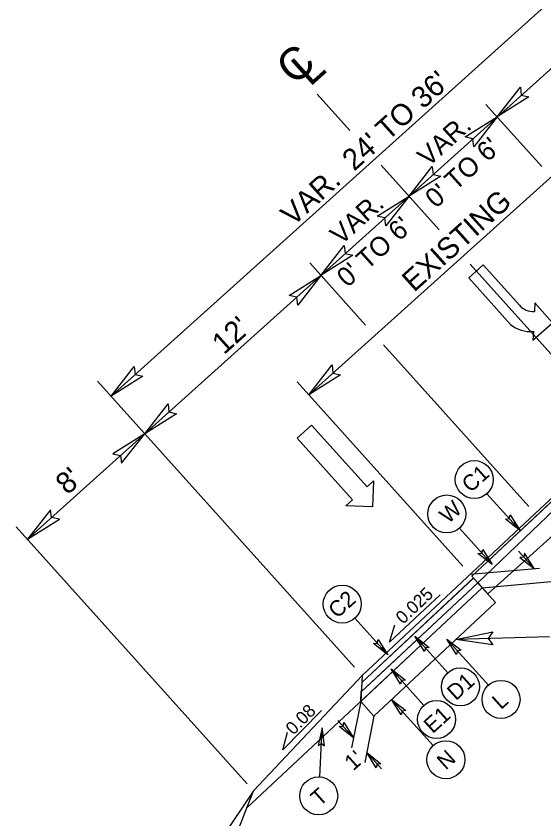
# Model space of a CAD drawing. Extents: x 2488411 to 2488707, y 383669 to 383962.
# Drawn here: x 2488590.73 to 2488617.46, y 383804.17 to 383844.82 of the extents above; entities that cross this region are included whole.
import ezdxf

# ---------------------------------------------------------------- set-up
doc = ezdxf.new("R2010")
doc.units = 0
for name, color, linetype in [('Old_Level_44', 7, 'Continuous'), ('Prop Dimension', 7, 'Continuous'), ('Prop DSN Text', 7, 'Continuous'), ('Prop Paint Stripe', 7, 'Continuous'), ('Prop Rip Rap Related Quantities Text', 7, 'Continuous'), ('Prop Roadway Profile Bench Mark Info Text', 7, 'Continuous'), ('Prop ROW RW Lines', 7, 'Continuous'), ('Sheet Data Field CELL', 7, 'Continuous'), ('Sheet Plan CELL', 7, 'Continuous'), ('Sheet Sticker Incomplete CELL', 7, 'Continuous'), ('Sheet Sticker Preliminary CELL', 7, 'Continuous'), ('Sheet Symbology CELL', 7, 'Continuous'), ('Sheet Title CELL', 7, 'Continuous'), ('Typical Hinge Slope Arterial CELL', 7, 'Continuous'), ('Typical Terminator CELL', 7, 'Continuous'), ('Typical Text ID Circle CELL', 7, 'Continuous')]:
    doc.layers.add(name, color=color, linetype=linetype)

msp = doc.modelspace()

# ---------------------------------------------------------------- linework, layer by layer
at = {"layer": 'Prop Dimension'}
msp.add_line((2488617.748, 383813.385), (2488612.992, 383813.253), dxfattribs=at)
at = {"layer": 'Prop DSN Text'}
for p, q in [((2488614.573, 383820.637), (2488616.234, 383818.788)), ((2488613.183, 383818.893), (2488614.844, 383817.045)), ((2488607.885, 383814.329), (2488609.547, 383812.481)), ((2488612.591, 383811.571), (2488610.929, 383813.42)), ((2488614.645, 383810.934), (2488612.544, 383813.271)), ((2488611.379, 383809.917), (2488609.717, 383811.766)), ((2488611.849, 383807.88), (2488609.748, 383810.218)), ((2488606.103, 383806.294), (2488606.235, 383808.777))]:
    msp.add_line(p, q, dxfattribs=at)
for centre in [(2488613.93, 383821.352), (2488612.54, 383819.608), (2488607.242, 383815.044), (2488613.234, 383810.856), (2488615.288, 383810.219), (2488612.022, 383809.202), (2488612.492, 383807.165), (2488606.052, 383805.334)]:
    msp.add_circle(centre, 0.962, dxfattribs=at)
at = {"layer": 'Prop Paint Stripe'}
for points in [[(2488615.748, 383819.561), (2488616.234, 383818.788), (2488615.51, 383819.354), (2488615.706, 383819.376)], [(2488614.358, 383817.818), (2488614.844, 383817.045), (2488614.12, 383817.611), (2488614.316, 383817.632)], [(2488616.247, 383817.408), (2488616.964, 383816.843), (2488616.478, 383817.623), (2488616.436, 383817.43)], [(2488609.06, 383813.254), (2488609.547, 383812.481), (2488608.823, 383813.047), (2488609.018, 383813.068)], [(2488611.416, 383812.647), (2488610.929, 383813.42), (2488611.653, 383812.854), (2488611.458, 383812.832)], [(2488613.031, 383812.498), (2488612.544, 383813.271), (2488613.268, 383812.705), (2488613.072, 383812.684)], [(2488610.204, 383810.993), (2488609.717, 383811.766), (2488610.441, 383811.2), (2488610.246, 383811.178)], [(2488610.235, 383809.445), (2488609.748, 383810.218), (2488610.472, 383809.651), (2488610.277, 383809.63)], [(2488606.342, 383807.87), (2488606.235, 383808.777), (2488606.027, 383807.881), (2488606.193, 383807.988)], [(2488607.329, 383809.046), (2488607.816, 383808.273), (2488607.092, 383808.839), (2488607.287, 383808.86)], [(2488608.971, 383806.756), (2488608.484, 383807.529), (2488609.208, 383806.963), (2488609.012, 383806.942)]]:
    msp.add_lwpolyline(points, close=True, dxfattribs=at)
at = {"layer": 'Prop Rip Rap Related Quantities Text'}
for p, q in [((2488613.805, 383816.458), (2488621.477, 383823.637)), ((2488617.012, 383819.63), (2488621.392, 383823.728)), ((2488608.251, 383811.432), (2488617.012, 383819.63)), ((2488608.207, 383810.596), (2488614.111, 383816.121)), ((2488608.232, 383811.072), (2488613.891, 383816.367)), ((2488614.332, 383815.876), (2488613.807, 383816.46)), ((2488602.404, 383804.714), (2488614.332, 383815.876)), ((2488608.86, 383810.755), (2488614.332, 383815.876)), ((2488614.332, 383815.876), (2488615, 383815.132)), ((2488615, 383815.132), (2488608.85, 383809.377)), ((2488608.251, 383811.432), (2488608.182, 383810.121)), ((2488608.182, 383810.121), (2488608.85, 383809.377))]:
    msp.add_line(p, q, dxfattribs=at)
at = {"layer": 'Prop Roadway Profile Bench Mark Info Text'}
for p, q in [((2488609.641, 383813.125), (2488612.2, 383815.52)), ((2488609.641, 383813.125), (2488609.907, 383814.001)), ((2488604.239, 383807.667), (2488606.191, 383809.653)), ((2488604.239, 383807.667), (2488604.468, 383808.553))]:
    msp.add_line(p, q, dxfattribs=at)
at = {"layer": 'Prop ROW RW Lines'}
for p, q in [((2488614.387, 383832.225), (2488613.651, 383831.564)), ((2488616.222, 383830.184), (2488614.387, 383832.225)), ((2488613.651, 383831.564), (2488615.767, 383829.21)), ((2488617.004, 383830.302), (2488616.98, 383829.857)), ((2488617.895, 383829.288), (2488617.004, 383830.302)), ((2488616.904, 383828.416), (2488617.895, 383829.288)), ((2488616.927, 383828.861), (2488616.904, 383828.416)), ((2488604.956, 383823.45), (2488605.692, 383824.112)), ((2488605.692, 383824.112), (2488608.5, 383820.989)), ((2488607.763, 383820.327), (2488604.956, 383823.45)), ((2488608.5, 383820.989), (2488608.834, 383821.29)), ((2488608.834, 383821.29), (2488608.774, 383819.965)), ((2488607.429, 383820.026), (2488607.763, 383820.327)), ((2488608.774, 383819.965), (2488607.429, 383820.026))]:
    msp.add_line(p, q, dxfattribs=at)
for centre, radius, start, end in [((2488616.951, 383830.835), 0.982, 221.9538, 271.612), ((2488616.763, 383830.424), 1.576, 230.6299, 275.9416)]:
    msp.add_arc(centre, radius, start, end, dxfattribs=at)
at = {"layer": 'Sheet Data Field CELL'}
for p, q in [((2488613.889, 383816.366), (2488608.232, 383811.072)), ((2488614.111, 383816.121), (2488613.889, 383816.366)), ((2488608.232, 383811.072), (2488608.207, 383810.596))]:
    msp.add_line(p, q, dxfattribs=at)
msp.add_lwpolyline([(2488608.207, 383810.596), (2488608.639, 383811.001), (2488614.111, 383816.121)], dxfattribs=at)
at = {"layer": 'Sheet Plan CELL'}
for p, q in [((2488598.022, 383793.579), (2488602.748, 383805.589)), ((2488602.748, 383805.589), (2488598.137, 383798.755))]:
    msp.add_line(p, q, dxfattribs=at)
at = {"layer": 'Sheet Sticker Incomplete CELL'}
msp.add_line((2488602.748, 383805.589), (2488608.251, 383811.432), dxfattribs=at)
at = {"layer": 'Sheet Sticker Preliminary CELL'}
for points in [[(2488616.698, 383840.724), (2488615.088, 383839.711), (2488616.267, 383841.219), (2488616.312, 383840.811)], [(2488613.478, 383838.698), (2488615.088, 383839.711), (2488613.909, 383838.203), (2488613.864, 383838.611)], [(2488612.238, 383836.715), (2488610.628, 383835.702), (2488611.807, 383837.21), (2488611.852, 383836.802)], [(2488609.018, 383834.689), (2488610.628, 383835.702), (2488609.449, 383834.194), (2488609.405, 383834.602)], [(2488607.779, 383832.706), (2488606.169, 383831.693), (2488607.348, 383833.201), (2488607.392, 383832.793)], [(2488604.558, 383830.679), (2488606.169, 383831.693), (2488604.989, 383830.185), (2488604.945, 383830.593)], [(2488597.147, 383826.59), (2488595.537, 383825.577), (2488596.716, 383827.085), (2488596.76, 383826.677)], [(2488607.16, 383826.658), (2488605.55, 383825.645), (2488606.729, 383827.153), (2488606.774, 383826.745)], [(2488598.858, 383824.686), (2488597.248, 383823.673), (2488598.427, 383825.181), (2488598.471, 383824.773)], [(2488596.068, 383822.179), (2488597.246, 383823.672), (2488595.622, 383822.66), (2488596.023, 383822.572)], [(2488592.477, 383819.819), (2488591.299, 383818.326), (2488592.924, 383819.338), (2488592.523, 383819.426)], [(2488615.981, 383819.191), (2488616.234, 383818.788), (2488615.857, 383819.083), (2488615.959, 383819.094)], [(2488614.591, 383817.447), (2488614.844, 383817.045), (2488614.467, 383817.34), (2488614.569, 383817.351)], [(2488611.183, 383813.017), (2488610.929, 383813.42), (2488611.306, 383813.125), (2488611.204, 383813.114)], [(2488614.875, 383812.982), (2488612.992, 383813.253), (2488614.867, 383813.638), (2488614.637, 383813.299)], [(2488609.293, 383812.883), (2488609.547, 383812.481), (2488609.17, 383812.776), (2488609.272, 383812.787)], [(2488609.971, 383811.363), (2488609.717, 383811.766), (2488610.094, 383811.471), (2488609.992, 383811.46)], [(2488606.291, 383808.304), (2488606.235, 383808.777), (2488606.127, 383808.31), (2488606.213, 383808.366)]]:
    msp.add_lwpolyline(points, close=True, dxfattribs=at)
at = {"layer": 'Sheet Symbology CELL'}
for p, q in [((2488614.111, 383816.121), (2488621.702, 383823.383)), ((2488608.207, 383810.596), (2488614.111, 383816.121)), ((2488613.805, 383816.458), (2488614.111, 383816.121)), ((2488614.111, 383816.121), (2488614.332, 383815.876)), ((2488614.332, 383815.876), (2488611.475, 383813.202)), ((2488611.475, 383813.202), (2488608.182, 383810.121)), ((2488611.475, 383813.202), (2488611.475, 383813.202)), ((2488608.182, 383810.121), (2488608.207, 383810.596))]:
    msp.add_line(p, q, dxfattribs=at)
for points in [[(2488621.559, 383823.543), (2488621.477, 383823.637), (2488613.805, 383816.458)], [(2488611.475, 383813.202), (2488611.475, 383813.202)]]:
    msp.add_lwpolyline(points, dxfattribs=at)
at = {"layer": 'Sheet Title CELL'}
for p, q in [((2488591.299, 383818.326), (2488629.958, 383853.078)), ((2488595.537, 383825.577), (2488622.298, 383849.634)), ((2488617.348, 383837.197), (2488614.515, 383840.348)), ((2488605.55, 383825.645), (2488621.168, 383839.684)), ((2488608.429, 383829.178), (2488605.596, 383832.33)), ((2488616.697, 383819.981), (2488609.332, 383828.174)), ((2488607.872, 383811.854), (2488594.856, 383826.333)), ((2488613.348, 383816.97), (2488604.957, 383826.304)), ((2488602.427, 383805.947), (2488590.726, 383818.963)), ((2488616.964, 383816.843), (2488616.169, 383817.727)), ((2488613.723, 383816.553), (2488617.241, 383816.867)), ((2488614.332, 383815.876), (2488617.829, 383816.189)), ((2488608.182, 383810.121), (2488607.716, 383807.767)), ((2488608.85, 383809.377), (2488608.384, 383807.024)), ((2488607.816, 383808.273), (2488607.021, 383809.157)), ((2488609.231, 383806.698), (2488608.484, 383807.529))]:
    msp.add_line(p, q, dxfattribs=at)
at = {"layer": 'Typical Terminator CELL'}
for p, q in [((2488607.637, 383839.029), (2488605.978, 383840.875)), ((2488612.155, 383834.003), (2488609.215, 383837.274)), ((2488623.395, 383821.5), (2488613.727, 383832.255))]:
    msp.add_line(p, q, dxfattribs=at)
at = {"layer": 'Typical Text ID Circle CELL'}
for p, q in [((2488614.617, 383815.559), (2488630.234, 383829.598)), ((2488614.111, 383816.121), (2488621.702, 383823.383)), ((2488614.617, 383815.559), (2488614.111, 383816.121))]:
    msp.add_line(p, q, dxfattribs=at)

# ---------------------------------------------------------------- texts
at = {"layer": 'Old_Level_44'}
for s, p in [('C1', (2488613.743, 383820.652)), ('W', (2488612.618, 383819.078)), ('C2', (2488606.986, 383814.281)), ('D1', (2488612.998, 383810.124)), ('L', (2488615.28, 383809.669)), ('E1', (2488611.82, 383808.456)), ('N', (2488612.484, 383806.615)), ('T', (2488606.098, 383804.768))]:
    msp.add_text(s, height=0.8, rotation=41.9538, dxfattribs=at).set_placement(p)
at = {"layer": 'Prop Roadway Profile Bench Mark Info Text'}
for s, rotation, p in [('0.025', 43.0996, (2488610.324, 383813.999)), ('0.08', 45.5023, (2488604.775, 383808.384))]:
    msp.add_text(s, height=0.6476, rotation=rotation, dxfattribs=at).set_placement(p)
at = {"layer": 'Sheet Title CELL'}
for s, height, p in [("VAR.  24' TO 36'", 1.08166, (2488604.741, 383834.142)), ('VAR.', 0.9735, (2488611.598, 383837.148)), ("0' TO 6'", 0.9735, (2488611.989, 383835.049)), ('EXISTING', 1.0817, (2488610.881, 383830.807)), ('VAR.', 0.9735, (2488607.18, 383833.189)), ("0' TO 6'", 0.9735, (2488607.513, 383831.04)), ("12'", 1.0817, (2488601.256, 383827.641)), ("8'", 1.0817, (2488593.332, 383820.54)), ("1'", 0.8, (2488607.803, 383806.571))]:
    msp.add_text(s, height=height, rotation=41.9538, dxfattribs=at).set_placement(p)
at = {"layer": 'Typical Hinge Slope Arterial CELL'}
for s, height, rotation, p in [('C', 1.64, 41.9538, (2488604.829, 383841.262)), ('L', 1.641, 41.9007, (2488605.609, 383841.21))]:
    msp.add_text(s, height=height, rotation=rotation, dxfattribs=at).set_placement(p)

doc.saveas('drawing.dxf')
